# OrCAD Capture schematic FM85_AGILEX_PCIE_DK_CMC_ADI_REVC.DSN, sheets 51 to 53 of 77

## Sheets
51 System MAX10 3: size B
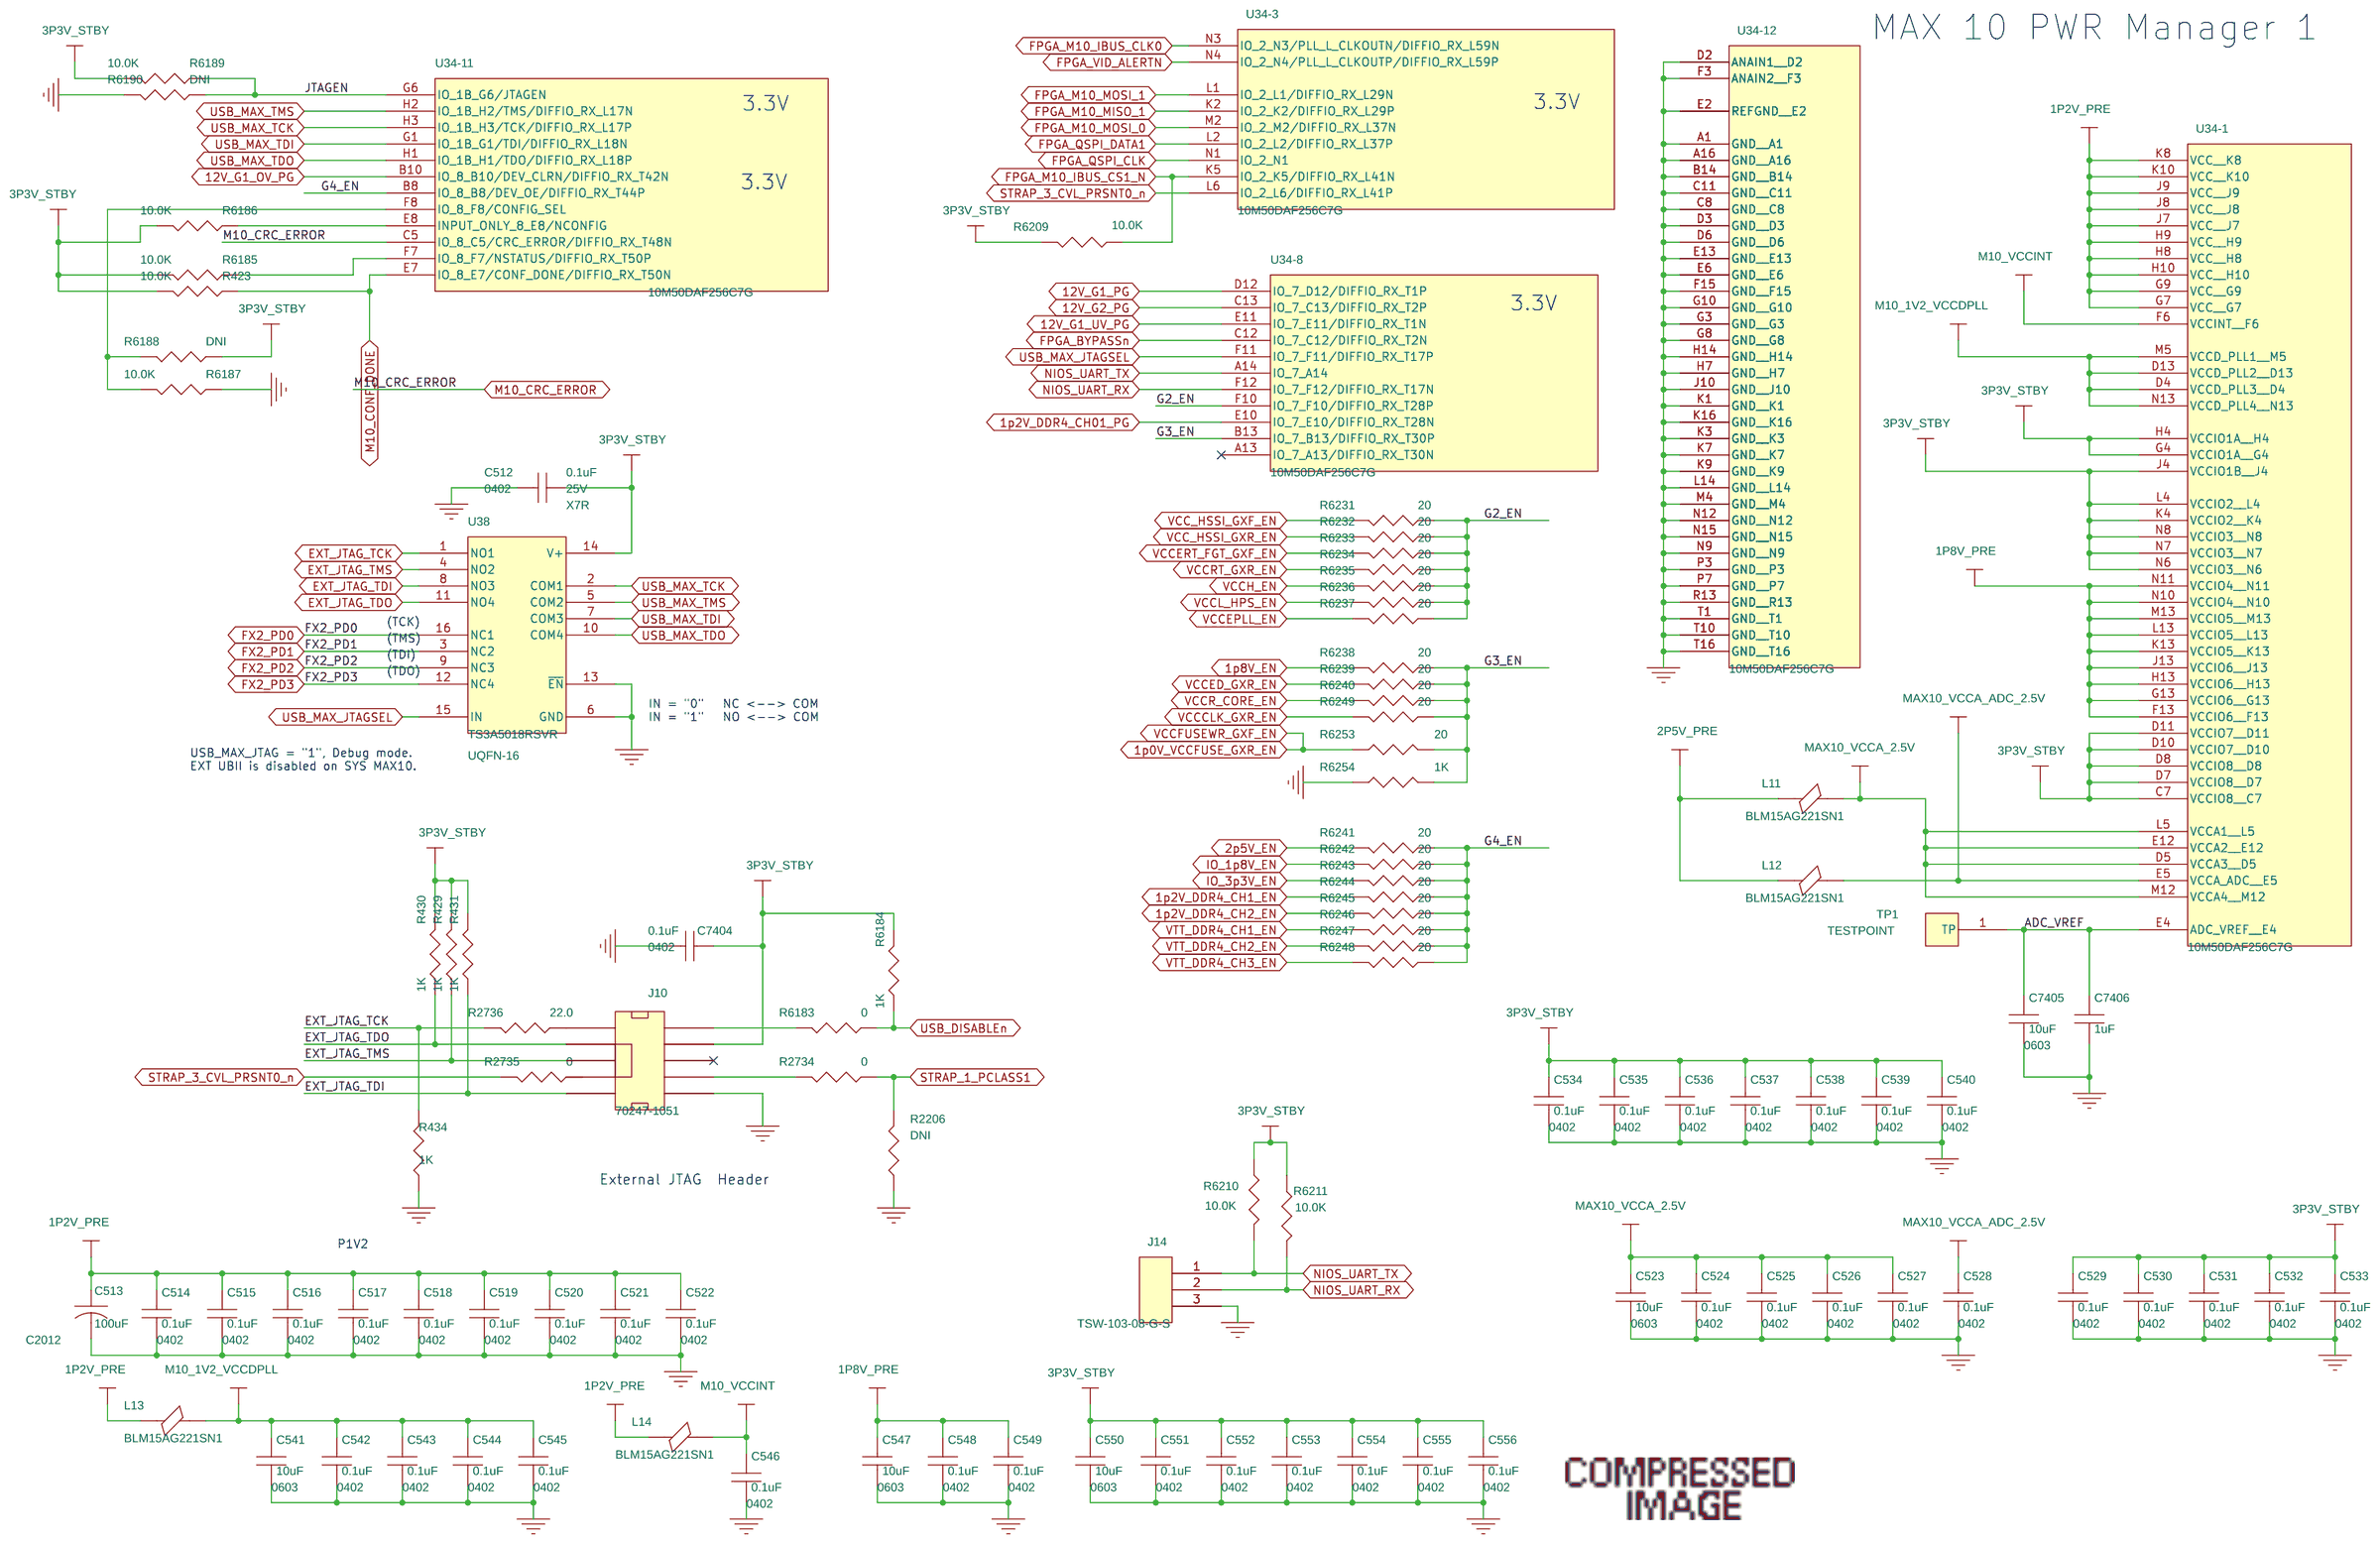
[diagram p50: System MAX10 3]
52 Level Shifter: size B
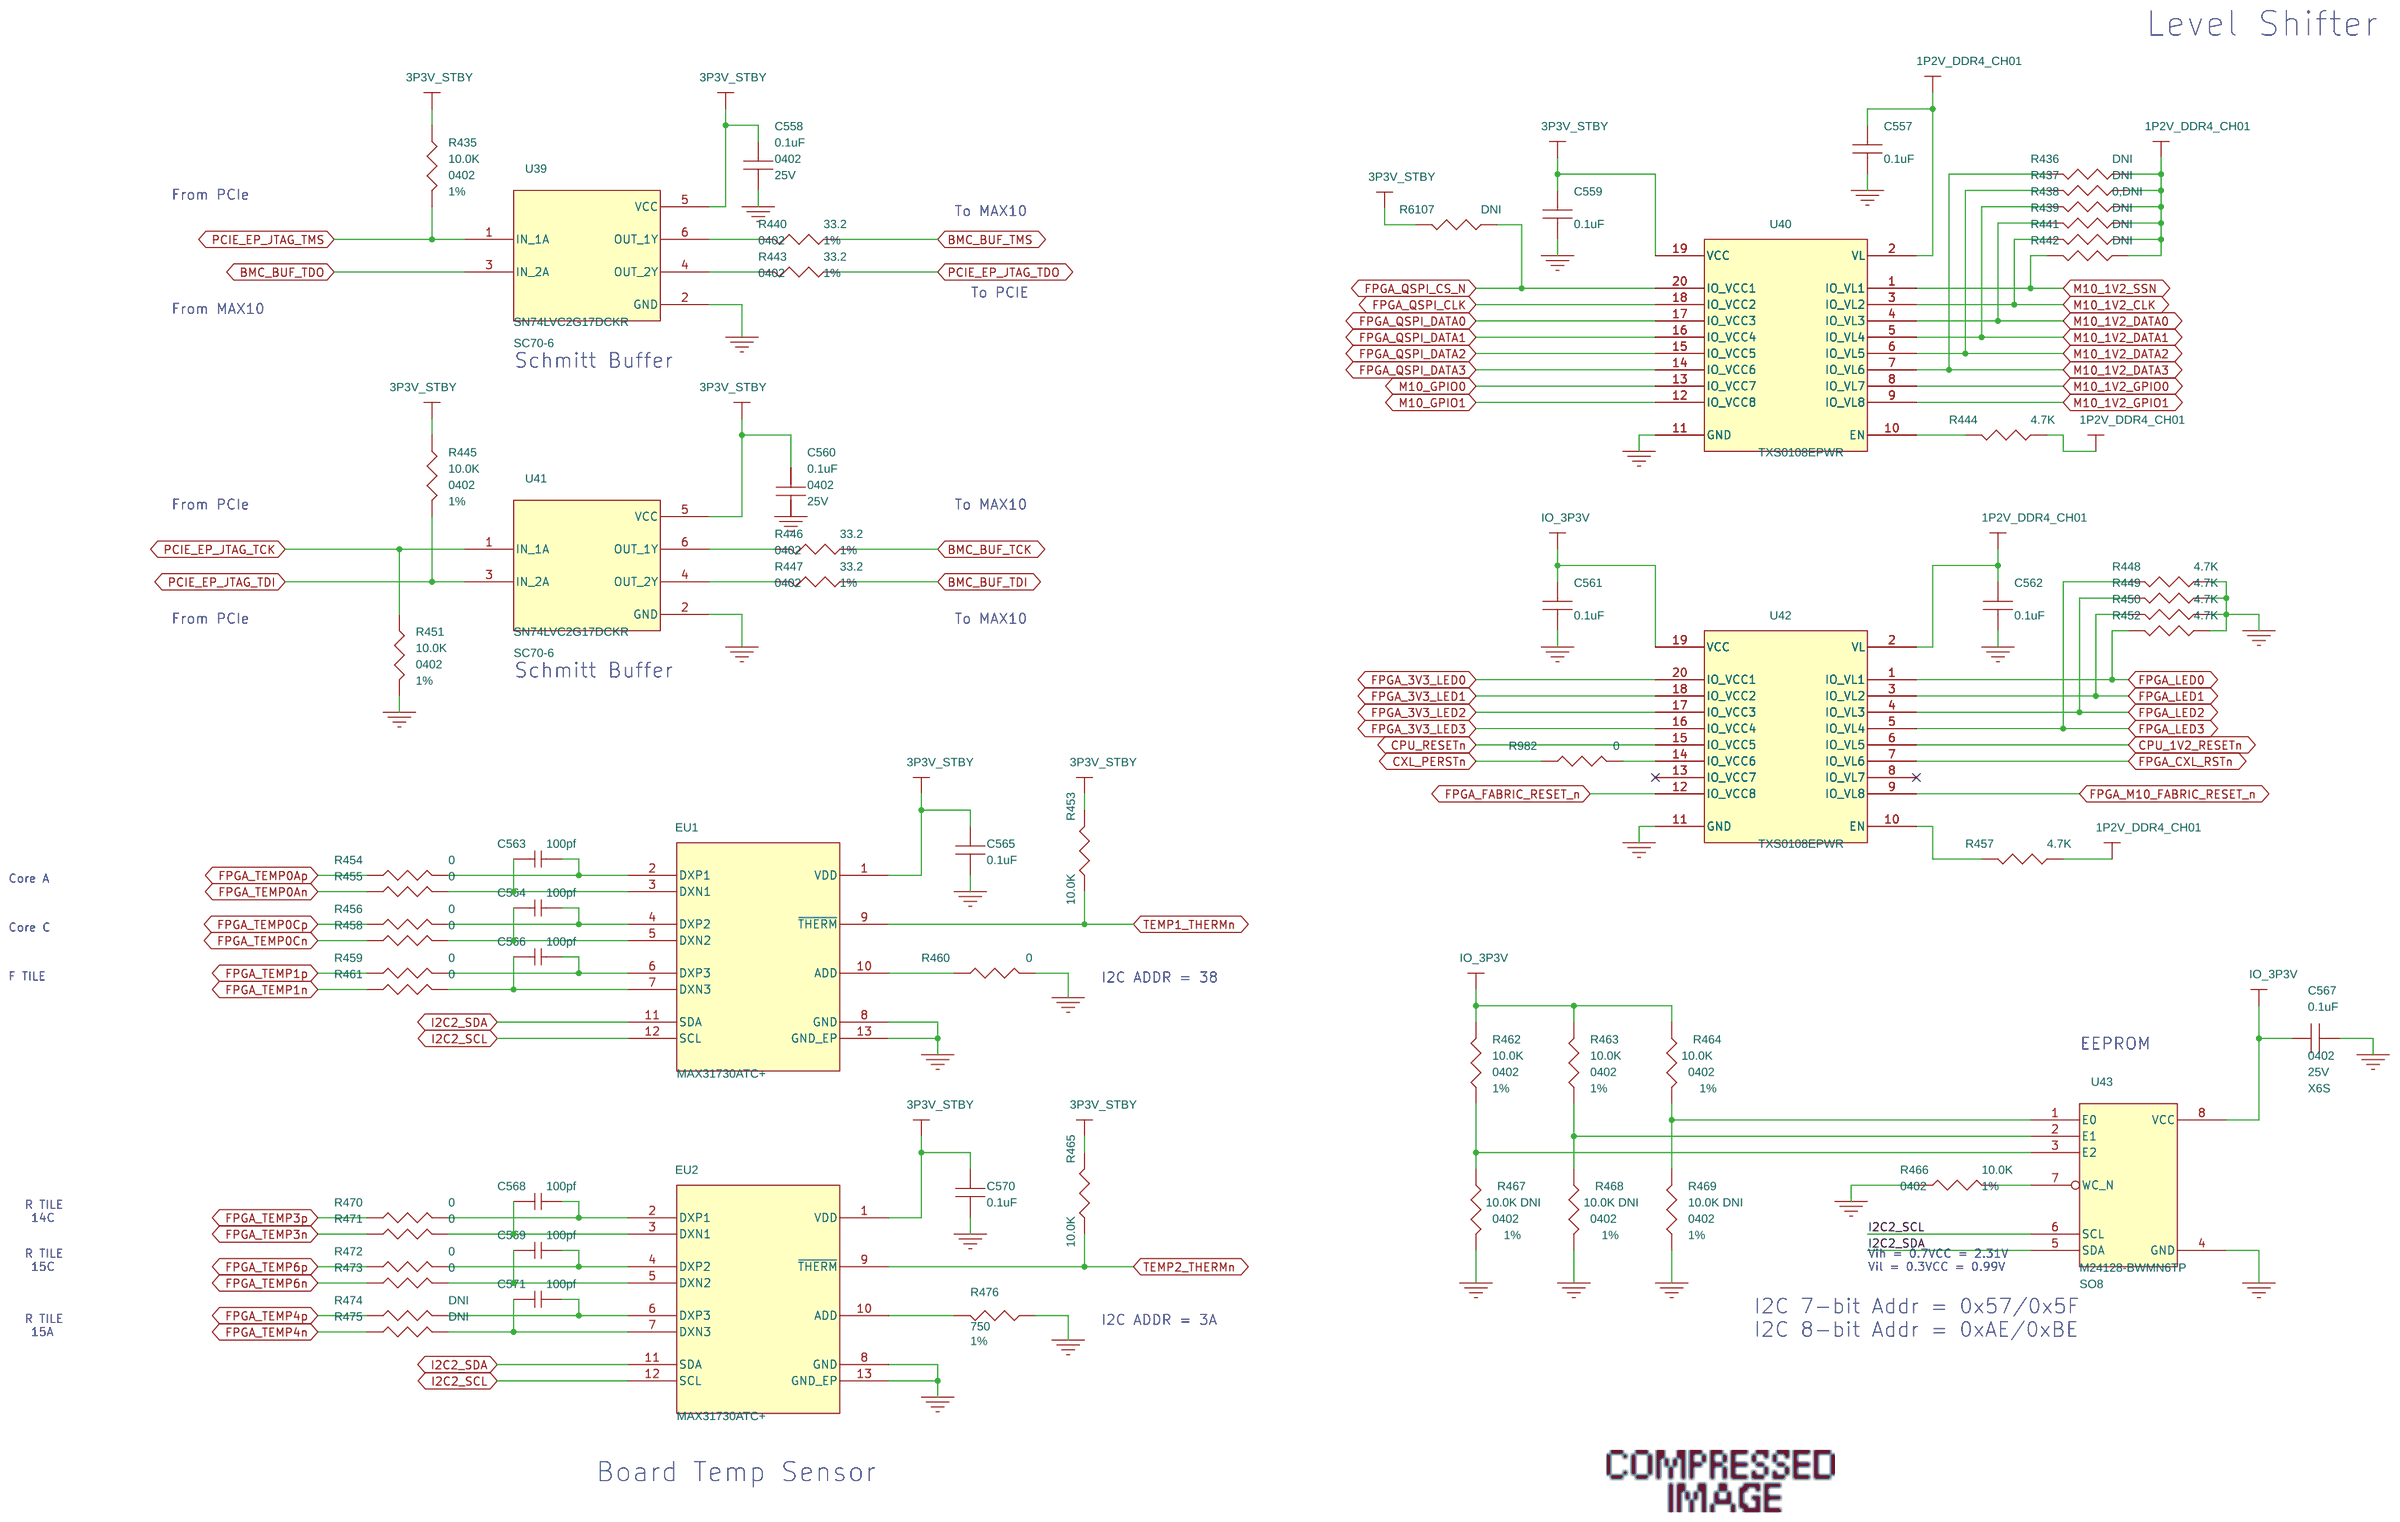
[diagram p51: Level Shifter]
53 Power Inputs: size Custom
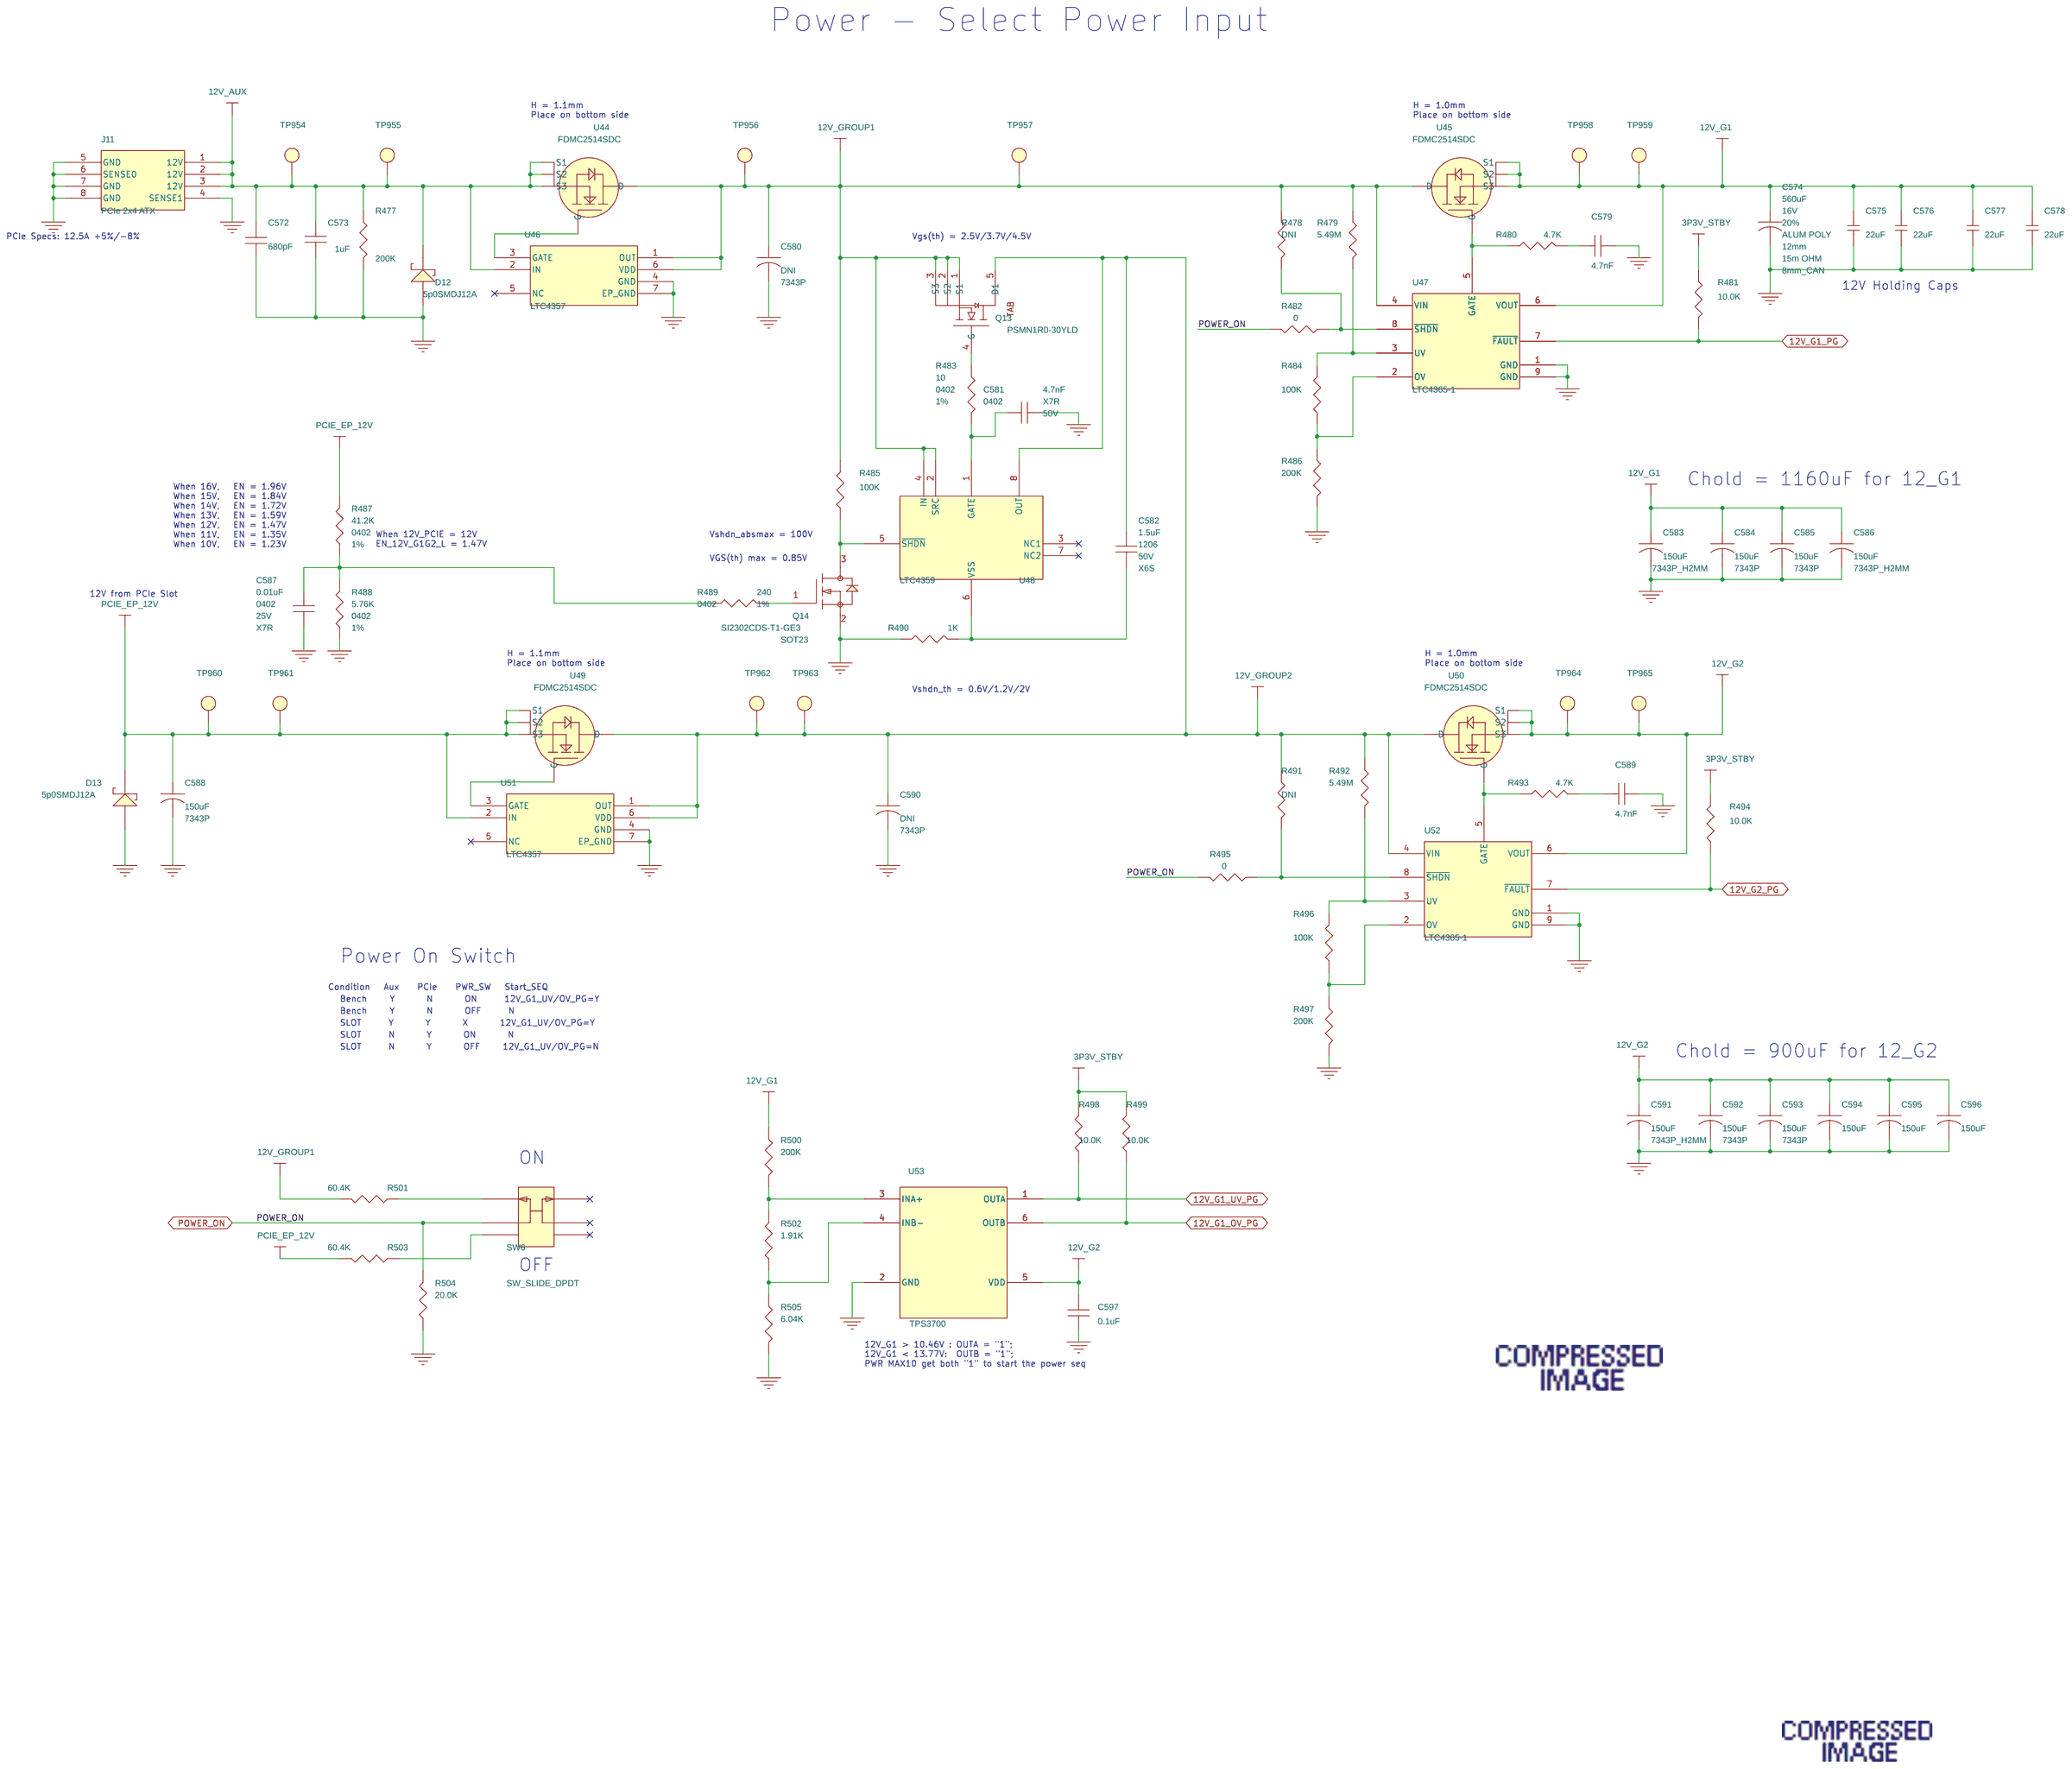
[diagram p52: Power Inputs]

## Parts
sheet Level Shifter
C557  0.1uF  [0402]
C558  0.1uF  [0402]
C559  0.1uF  [0402]
C560  0.1uF  [0402]
C561  0.1uF  [0402]
C562  0.1uF  [0402]
C563  100pf  [0402]
C564  100pf  [0402]
C565  0.1uF  [0402]
C566  100pf  [0402]
C567  0.1uF  [0402]
C568  100pf  [0402]
C569  100pf  [0402]
C570  0.1uF  [0402]
C571  100pf  [0402]
EU1  MAX31730ATC+  [lcc12_s30_50df25x17ma]
EU2  MAX31730ATC+  [lcc12_s30_50df25x17ma]
R435  10.0K  [0402]
R436  DNI  [0402]
R437  DNI  [0402]
R438  0,DNI  [0402]
R439  DNI  [0402]
R440  33.2  [0402]
R441  DNI  [0402]
R442  DNI  [0402]
R443  33.2  [0402]
R444  4.7K  [0402]
R445  10.0K  [0402]
R446  33.2  [0402]
R447  33.2  [0402]
R448  4.7K  [0402]
R449  4.7K  [0402]
R450  4.7K  [0402]
R451  10.0K  [0402]
R452  4.7K  [0402]
R453  10.0K  [0402]
R454  0  [0402]
R455  0  [0402]
R456  0  [0402]
R457  4.7K  [0402]
R458  0  [0402]
R459  0  [0402]
R460  0  [0402]
R461  0  [0402]
R462  10.0K  [0402]
R463  10.0K  [0402]
R464  10.0K  [0402]
R465  10.0K  [0402]
R466  10.0K  [0402]
R467  10.0K DNI  [0402]
R468  10.0K DNI  [0402]
R469  10.0K DNI  [0402]
R470  0  [0402]
R471  0  [0402]
R472  0  [0402]
R473  0  [0402]
R474  DNI  [0402]
R475  DNI  [0402]
R476  750  [0402]
R982  0  [0402]
R6107  DNI  [0402]
U39  SN74LVC2G17DCKR  [SC70-6]
U40  TXS0108EPWR  [20-TSSOP]
U41  SN74LVC2G17DCKR  [SC70-6]
U42  TXS0108EPWR  [20-TSSOP]
U43  M24128-BWMN6TP  [SO8]
sheet Power Inputs
C572  680pF  [0402]
C573  1uF  [0402]
C574  560uF  [8mm_CAN]
C575  22uF  [1206]
C576  22uF  [1206]
C577  22uF  [1206]
C578  22uF  [1206]
C579  4.7nF  [0402]
C580  DNI  [7343P]
C581  4.7nF  [0402]
C582  1.5uF  [1206]
C583  150uF  [7343P_H2MM]
C584  150uF  [7343P]
C585  150uF  [7343P]
C586  150uF  [7343P_H2MM]
C587  0.01uF  [0402]
C588  150uF  [7343P]
C589  4.7nF  [0402]
C590  DNI  [7343P]
C591  150uF  [7343P_H2MM]
C592  150uF  [7343P]
C593  150uF  [7343P]
C594  150uF  [7343P_H2MM]
C595  150uF  [7343P_H2MM]
C596  150uF  [7343P_H2MM]
C597  0.1uF  [0402]
D12  5p0SMDJ12A  [TVS_5p0SMDJ12A]
D13  5p0SMDJ12A  [TVS_5p0SMDJ12A]
J11  PCIe 2x4 ATX  [MLX_SD-5569_8POS_RA]
Q13  PSMN1R0-30YLD  [NFET_PSMN1R0-30YLD]
Q14  SI2302CDS-T1-GE3  [SOT23]
R477  200K  [0402]
R478  DNI  [0402]
R479  5.49M  [0402]
R480  4.7K  [0402]
R481  10.0K  [0402]
R482  0  [0402]
R483  10  [0402]
R484  100K  [0402]
R485  100K  [0402]
R486  200K  [0402]
R487  41.2K  [0402]
R488  5.76K  [0402]
R489  240  [0402]
R490  1K  [0402]
R491  DNI  [0402]
R492  5.49M  [0402]
R493  4.7K  [0402]
R494  10.0K  [0402]
R495  0  [0402]
R496  100K  [0402]
R497  200K  [0402]
R498  10.0K  [0402]
R499  10.0K  [0402]
R500  200K  [0402]
R501  60.4K  [0402]
R502  1.91K  [0402]
R503  60.4K  [0402]
R504  20.0K  [0402]
R505  6.04K  [0402]
SW6  SW_SLIDE_DPDT  [EG2207]
TP954  TESTPOINT  [30MIL_TP]
TP955  TESTPOINT  [30MIL_TP]
TP956  TESTPOINT  [30MIL_TP]
TP957  TESTPOINT  [30MIL_TP]
TP958  TESTPOINT  [30MIL_TP]
TP959  TESTPOINT  [30MIL_TP]
TP960  TESTPOINT  [30MIL_TP]
TP961  TESTPOINT  [30MIL_TP]
TP962  TESTPOINT  [30MIL_TP]
TP963  TESTPOINT  [30MIL_TP]
TP964  TESTPOINT  [30MIL_TP]
TP965  TESTPOINT  [30MIL_TP]
U44  FDMC2514SDC  [FDMC8878_VER2]
U45  FDMC2514SDC  [FDMC8878_VER2]
U46  LTC4357  [dfn6_epad]
U47  LTC4365-1  [DFN8-EPAD_3X2]
U48  LTC4359  [MSOP-8]
U49  FDMC2514SDC  [FDMC8878_VER2]
U50  FDMC2514SDC  [FDMC8878_VER2]
U51  LTC4357  [dfn6_epad]
U52  LTC4365-1  [DFN8-EPAD_3X2]
U53  TPS3700  [DDC]
sheet System MAX10 3
C512  0.1uF  [0402]
C513  100uF  [C2012]
C514  0.1uF  [0402]
C515  0.1uF  [0402]
C516  0.1uF  [0402]
C517  0.1uF  [0402]
C518  0.1uF  [0402]
C519  0.1uF  [0402]
C520  0.1uF  [0402]
C521  0.1uF  [0402]
C522  0.1uF  [0402]
C523  10uF  [0603]
C524  0.1uF  [0402]
C525  0.1uF  [0402]
C526  0.1uF  [0402]
C527  0.1uF  [0402]
C528  0.1uF  [0402]
C529  0.1uF  [0402]
C530  0.1uF  [0402]
C531  0.1uF  [0402]
C532  0.1uF  [0402]
C533  0.1uF  [0402]
C534  0.1uF  [0402]
C535  0.1uF  [0402]
C536  0.1uF  [0402]
C537  0.1uF  [0402]
C538  0.1uF  [0402]
C539  0.1uF  [0402]
C540  0.1uF  [0402]
C541  10uF  [0603]
C542  0.1uF  [0402]
C543  0.1uF  [0402]
C544  0.1uF  [0402]
C545  0.1uF  [0402]
C546  0.1uF  [0402]
C547  10uF  [0603]
C548  0.1uF  [0402]
C549  0.1uF  [0402]
C550  10uF  [0603]
C551  0.1uF  [0402]
C552  0.1uF  [0402]
C553  0.1uF  [0402]
C554  0.1uF  [0402]
C555  0.1uF  [0402]
C556  0.1uF  [0402]
C7404  0.1uF  [0402]
C7405  10uF  [0603]
C7406  1uF  [0402]
J10  70247-1051  [Molex_70247-1051]
J14  TSW-103-08-G-S  [1x3_HDR_TH]
L11  BLM15AG221SN1  [0402]
L12  BLM15AG221SN1  [0402]
L13  BLM15AG221SN1  [0402]
L14  BLM15AG221SN1  [0402]
R423  10.0K  [0402]
R429  1K  [0402]
R430  1K  [0402]
R431  1K  [0402]
R434  1K  [0402]
R2206  DNI  [0402]
R2734  0  [0402]
R2735  0  [0402]
R2736  22.0  [0402]
R6183  0  [0402]
R6184  1K  [0402]
R6185  10.0K  [0402]
R6186  10.0K  [0402]
R6187  10.0K  [0402]
R6188  DNI  [0402]
R6189  10.0K  [0402]
R6190  DNI  [0402]
R6209  10.0K  [0402]
R6210  10.0K  [0402]
R6211  10.0K  [0402]
R6231  20  [0402]
R6232  20  [0402]
R6233  20  [0402]
R6234  20  [0402]
R6235  20  [0402]
R6236  20  [0402]
R6237  20  [0402]
R6238  20  [0402]
R6239  20  [0402]
R6240  20  [0402]
R6241  20  [0402]
R6242  20  [0402]
R6243  20  [0402]
R6244  20  [0402]
R6245  20  [0402]
R6246  20  [0402]
R6247  20  [0402]
R6248  20  [0402]
R6249  20  [0402]
R6253  20  [0402]
R6254  1K  [0402]
TP1  TESTPOINT  [30mil_TP]
U34  10M50DAF256C7G  [256FBGA]  (sections -1,-10,-11,-12,-2,-3,-4,-5,-6,-7,-8,-9)
U38  TS3A5018RSVR  [UQFN-16]

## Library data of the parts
C557 C559 C561 C562 = CAP: CAPC,  X7R, 0402, 0.1uF, 25V, ±20%; Item Num: K13660-001; LIFECYCLE_PHASE: Active; Lead Free Status: Lead Free; MFR_LIFECYCLE: Active; Manufacturer: Murata; Manufacturer Part Num: GRM155R71E104KE14D; Num Pins: 2; PART_SUBCLASS: CAPACITORS; Part Class: CAPACITORS; RATED_VOLTAGE: 25V; RoHS Compliant: RoHS Compliant; Tolerance: +80%/-20%
C558 C560 = CAP: CAPC,  X7R, 0402, 0.1uF, 25V, ±20%; Item Num: K13660-001; LIFECYCLE_PHASE: Active; Lead Free Status: Lead Free; Manufacturer: Murata; Manufacturer Part Num: GRM155R71E104KE14D; Num Pins: 2; Part Class: CAPACITORS; RATED_VOLTAGE: 25V; RoHS Compliant: RoHS Compliant; Tolerance: +80%/-20%
C563 C564 C566 C568 C569 C571 = Cap,_NP,_0402: CAP, CERAMIC, 100pF, 0402, 5%, 50VDC, NPO; Item Num: K13768-001; Manufacturer: Murata; Manufacturer Part Num: GRM1555C1H101JA01D
C565 C570 C597 = CAP: CAPC,  X7R, 0402, 0.1uF, 25V, ±20%; AGILE_LINK: http://sj-agile9app/Agile/PLMServlet?action=OpenEmailObject&classid=10000&objid=213459527; Item Num: K13660-001; LIFECYCLE_PHASE: Active; Lead Free Status: Lead Free; MFR_LIFECYCLE: Active; Manufacturer: Murata; Manufacturer Part Num: GRM155R71E104KE14D; Num Pins: 2; PART_SUBCLASS: CAPACITORS; Part Class: CAPACITORS; RATED_VOLTAGE: 25V; RoHS Compliant: RoHS Compliant; TOLERANCE: +80%/-20%
C567 = CAP: CAPC,  X7R, 0402, 0.1uF, 25V, ±20%; Dielectric: X6S; Item Num: K13660-001; LIFECYCLE_PHASE: Active; Lead Free Status: Lead Free; Manufacturer: Murata; Manufacturer Part Num: GRM155R71E104KE14D; Num Pins: 2; Part Class: CAPACITORS; RATED_VOLTAGE: 25V; RoHS Compliant: RoHS Compliant; Tolerance: 10%
EU1 EU2 = MAX31730ATC: IC, MAX31730, 3-Ch Remote Temp Sensor; Item Num: K87190-001; Manufacturer: Maxim
R435 R445 R451 = RESISTOR: RES,10.0K OHMS,1.0%,1/16W, 0402; AGILE_LINK: http://sj-agile9app/Agile/PLMServlet?action=OpenEmailObject&classid=10000&objid=146548997; Agile IPN: P02-11364R; Item Num: K28115-001; LIFECYCLE_PHASE: Active; Lead Free Status: No; MFR_LIFECYCLE: Active; Manufacturer: Panasonic; Manufacturer Part Num: ERJ-2RKF1002X; Num Pins: 2; PART_SUBCLASS: RESISTORS; POWER: 1/16W; RESISTANCE: 10K; RoHS Compliant: Yes; TOLERANCE: 1%
R436 R437 R439 R441 R442 R444 R448-R450 R452 R457 R480 R493 R6107 = RESISTOR: RES 4.7K OHM 1/16W 5% 0402 SMD; Item Num: A93549-020; Lead Free Status: No; Manufacturer: Panasonic; Manufacturer Part Num: ERJ-2GEJ472X; Manufacturer's Part No.: ERJ-2GEJ472X; Num Pins: 2; Part Class: RESISTORS; Price: 0; RoHS Compliant: Yes
R438 = RESISTOR: RES D,0402,0.00 OHM,5.00%,1/16W; Item Num: A93549-001; Lead Free Status: No; Manufacturer: Panasonic; Manufacturer Part Num: ERJ-2GEJ472X; Manufacturer's Part No.: ERJ-2GEJ472X; Num Pins: 2; Part Class: RESISTORS; Price: 0; RoHS Compliant: Yes
R440 R443 R446 R447 = RESISTOR: RES,33.2 OHMS,1.0%,1/16W,0402; AGILE_LINK: http://sj-agile9app/Agile/PLMServlet?action=OpenEmailObject&classid=10000&objid=146932246; Agile IPN: P02-11379R; Item Num: E61624-001; LIFECYCLE_PHASE: Active; MFR_LIFECYCLE: Active; Manufacturer: Panasonic; Manufacturer Part Num: ERJ-2RKF33R2X; Num Pins: 2; PART_SUBCLASS: RESISTORS; POWER: 1/16W; RESISTANCE: 10; RoHS Compliant: RoHS Compliant; TOLERANCE: 1%
R423 R453 R465 R481 R494 R498 R499 R6185-R6187 R6189 R6209-R6211 = RESISTOR: RES,10.0K OHMS,1.0%,1/16W, 0402; AGILE_LINK: http://sj-agile9app/Agile/PLMServlet?action=OpenEmailObject&classid=10000&objid=146548997; Item Num: K28115-001; LIFECYCLE_PHASE: Active; Lead Free Status: No; MFR_LIFECYCLE: Active; Manufacturer: Panasonic; Manufacturer Part Num: ERJ-2RKF1002X; Num Pins: 2; PART_SUBCLASS: RESISTORS; POWER: 1/16W; RoHS Compliant: Yes; TOLERANCE: +/-1%
R454-R456 R458-R461 R470-R473 R982 = RESISTOR: RES ZERO OHM 1/16W 5% 0402 SMD; Altera Part No.: P02-14020R; Item Num: H30887-001; Lead Free Status: No; Manufacturer: Panasonic; Manufacturer Part Num: ERJ-2GE0R00X; Num Pins: 2; Part Class: RESISTORS; RoHS Compliant: Yes; Tolerance: 5%
R462-R464 R466-R469 = RESISTOR: RES,10.0K OHMS,1.0%,1/16W, 0402; AGILE_LINK: http://sj-agile9app/Agile/PLMServlet?action=OpenEmailObject&classid=10000&objid=146548997; Item Num: K28115-001; LIFECYCLE_PHASE: Active; Lead Free Status: No; MFR_LIFECYCLE: Active; Manufacturer: Panasonic; Manufacturer Part Num: ERJ-2RKF1002X; Num Pins: 2; PART_SUBCLASS: RESISTORS; POWER: 1/16W; RESISTANCE: 10K; RoHS Compliant: Yes; TOLERANCE: 1%
R474 R475 = RESISTOR: RES ZERO OHM 1/16W 5% 0402 SMD; Altera Part No.: P02-14020R; Item Num: H30887-001; Lead Free Status: No; Manufacturer: Panasonic; Manufacturer Part Num: ERJ-2GE0R00X; Num Pins: 2; Part Class: RESISTORS; Price: 0; RoHS Compliant: Yes; Tolerance: 5%
R476 = RESISTOR: RES SMD 750 OHM 1% 1/16W 0402; Item Num: G60609-020; Manufacturer: Yageo; Manufacturer Part Num: RC0402FR-07750RL; Num Pins: 2; Part Class: Resistors; TOLERANCE: 1%
U39 U41 = SN74LVC2G17DCKR: IC - Dual Schmitt-Trigger Buffer; Agile IPN: P01-18210R; Item Num: K21749-001; Manufacturer: Texas Instruments
U40 U42 = MAX3002EUP+T: IC TRNSLTR BIDIRECTIONAL 20TSSOP; Item Num: G13285-001; Manufacturer: Texa Instrument
U43 = M24128: IC EEPROM 128KBIT 400KHZ 8SO; Item Num: K21780-001; Manufacturer: STMicroelectronics
C572 = CAP: CAP - CER, 680pF, 10%, 50V, X7R, 0402; Item Num: A36096-015; LIFECYCLE_PHASE: Active; MFR_LIFECYCLE: Active; Manufacturer: Murata; Manufacturer Part Num: GRM155R71H681KA01D; Num Pins: 2; PART_SUBCLASS: CAPACITORS; RATED_VOLTAGE: 50V; RoHS Compliant: RoHS Compliant; TOLERANCE: +/-10%
C573 = CAP: CAP - CER, 1UF, 25V, 10%, X5R, 0402; Item Num: H29050-001; Lead Free Status: Yes; Manufacturer: TDK Electronics; Manufacturer Part Num: CGB2A1X5R1E105K033BC; Num Pins: 2; Part Class: CAPACITORS; RoHS Compliant: Yes
C574 = PCAP: 560µF ±20% 16V Aluminum Polymer Capacitor Radial, Can - SMD 14 mOhm 5000 Hrs @ 105°C; AGILE_LINK: http://sj-agile9app/Agile/PLMServlet?action=OpenEmailObject&classid=10000&objid=257237054; ESR: 15m OHM; Height: 12mm; Item Num: K22159-001; LIFECYCLE_PHASE: Active; Lead Free Status: Lead Free; MFR_LIFECYCLE: Active; Manufacturer: Panasonic; Manufacturer Part Num: 16SVPF560M; Num Pins: 2; PART_SUBCLASS: CAPACITORS; RATED_VOLTAGE: 16V; RoHS Compliant: RoHS Compliant; TOLERANCE: 20%; TYPE: ALUM POLY
C575-C578 = Cap,_NP,_1206: CAP - CER, 22UF, 25V, 10%, X5R, 1206; Item Num: K28232-001; Manufacturer: Murata; Manufacturer Part Num: GRM31CR61E226KE15L
C579 C589 = CAP: CAP CER 4700PF 50V 10% X7R 0402; AGILE_LINK: http://sj-agile9app/Agile/PLMServlet?action=OpenEmailObject&classid=10000&objid=256989767; CAPACITANCE: 15000pF; Item Num: K13700-001; LIFECYCLE_PHASE: Active; Lead Free Status: Lead Free; MFR_LIFECYCLE: Active; Manufacturer: Murata; Manufacturer Part Num: GRM155R71H472KA01J; Num Pins: 2; PART_SUBCLASS: CAPACITORS; RATED_VOLTAGE: 50V; RoHS Compliant: RoHS Compliant; TOLERANCE: 10%
C580 = PCAP: CAP - TANT POLYMER,150UF,16V,50MOHM ESR20%, 7343*1.8MM; CAPACITANCE: 150uF; LIFECYCLE_PHASE: Active; Lead Free Status: Lead Free; MFR_LIFECYCLE: Active; Manufacturer: Panasonic; Manufacturer Part Num: 16TQC150MYF; Num Pins: 2; PART_SUBCLASS: CAPACITORS; RATED_VOLTAGE: 16V; RoHS Compliant: RoHS Compliant; TOLERANCE: +/-20%
C581 = CAP: CAP CER 4700PF 50V 10% X7R 0402; AGILE_LINK: http://sj-agile9app/Agile/PLMServlet?action=OpenEmailObject&classid=10000&objid=256989767; CAPACITANCE: 4700pF; Item Num: K13700-001; LIFECYCLE_PHASE: Active; Lead Free Status: Lead Free; MFR_LIFECYCLE: Active; Manufacturer: Murata; Manufacturer Part Num: GRM155R71H472KA01J; Num Pins: 2; PART_SUBCLASS: CAPACITORS; RATED_VOLTAGE: 50V; RoHS Compliant: RoHS Compliant; TOLERANCE: 10%; Temperature Coefficient: X7R
C582 = CAP: CAP CER 1.5UF 50V X6S 1206; CAPACITANCE: 0.1uF; Dielectric: X6S; Item Num: K19472-001; LIFECYCLE_PHASE: Active; Lead Free Status: Lead Free; Manufacturer: Murata; Manufacturer Part Num: GRT31CC81H155KE01L; Num Pins: 2; Part Class: CAPACITORS; RATED_VOLTAGE: 50V; RoHS Compliant: RoHS Compliant; Tolerance: 10%
C583 C586 C591 C594-C596 = PCAP: CAPS,TA-P,D20,150.00uF,16.00V,+/- 20%,D20; Item Num: H97831-001; LIFECYCLE_PHASE: Active; Lead Free Status: Lead Free; MFR_LIFECYCLE: Active; Manufacturer: Panasonic; Manufacturer Part Num: 1CTQC15173F1; Num Pins: 2; PART_SUBCLASS: CAPACITORS; RATED_VOLTAGE: 16V; RoHS Compliant: RoHS Compliant; TOLERANCE: +/-20%
C584 C585 C588 C592 C593 = PCAP: CAP - TANT POLYMER,150UF,16V,50MOHM ESR20%, 7343*1.8MM; Item Num: G46681-001; LIFECYCLE_PHASE: Active; Lead Free Status: Lead Free; MFR_LIFECYCLE: Active; Manufacturer: Panasonic; Manufacturer Part Num: 16TQC150MYF; Num Pins: 2; PART_SUBCLASS: CAPACITORS; RATED_VOLTAGE: 16V; RoHS Compliant: RoHS Compliant; TOLERANCE: +/-20%
C587 = CAP: CAP CER 10000PF 25V X7R 0402; AGILE_LINK: http://sj-agile9app/Agile/PLMServlet?action=OpenEmailObject&classid=10000&objid=242850622; Item Num: A36096-008; LIFECYCLE_PHASE: Active; MFR_LIFECYCLE: Active; Manufacturer: Murata; Manufacturer Part Num: GRM155R71E103KA01D; Num Pins: 2; PACKAGING: Tape & Reel (TR); PART_SUBCLASS: CAPACITORS; RATED_VOLTAGE: 25V; RoHS Compliant: RoHS Compliant; TOLERANCE: 10%; Temperature Coefficient: X7R
C590 = PCAP: CAP - TANT POLYMER,150UF,16V,50MOHM ESR20%, 7343*1.8MM; CAPACITANCE: 150uF; Item Num: G46681-001; LIFECYCLE_PHASE: Active; Lead Free Status: Lead Free; MFR_LIFECYCLE: Active; Manufacturer: Panasonic; Manufacturer Part Num: 16TQC150MYF; Num Pins: 2; PART_SUBCLASS: CAPACITORS; RATED_VOLTAGE: 16V; RoHS Compliant: RoHS Compliant; TOLERANCE: +/-20%
D12 D13 = TVS_5p0SMDJ12A: TVS DIODE 12VWM 19.9VC SMD; Item Num: J31279-001; Manufacturer: Littelfuse Inc.; Manufacturer Part Num: 5.0SMDJ12A
J11 = 2X4_PCIE_ATX_1: CONN,PCIE ATX,8POS HDR,4.2MM,R/A; Item Num: K11298-001; Manufacturer: MOLEX CONNECTOR CORPORATION; Manufacturer Part Num: 45586-0005
Q13 = PSMN1R0-30YLD_0: MOSFET, N-Channel, 30V, 1mOhm, 300A; Item Num: K21466-001; Manufacturer: Nexperia USA Inc.
Q14 = PWRMOSFET_EN_GSD_1: MOSFET N-CH 20V 2.6A SOT23-3; Item Num: K69552-001; Manufacturer: Vishay Siliconix
R477 R486 R497 = RES: RES - 200K OHM, 1/16W, 1%, 0402 SMD; Item Num: A93548-186; Manufacturer: Panasonic; Manufacturer Part Num: ERJ-2RKF2003X; Package: SMD; Part Class: RESISTORS; Type: Resistor
R478 R484 R485 R491 R496 = RESISTOR: RES, 100K OHMS, 1.0%, 1/16W, 0402; Item Num: E86804-001; Lead Free Status: No; Manufacturer: Panasonic; Manufacturer Part Num: ERJ-2RKF1003X; Num Pins: 2; Part Class: Resistors; Price: 0; RoHS Compliant: Yes
R479 R492 = RESISTOR: RES - 5.49M OHM, 1/16W, 1%, 0402 SMD; Item Num: K16257-001; Lead Free Status: Yes; Manufacturer: Vishay; Manufacturer Part Num: CRCW04025M49FKED; Num Pins: 2; Part Class: Resistors
R482 R495 = RES_0_OHM_5%_1_16W_0402_SMD: Item Num: H30887-001
R483 = RESISTOR: RES, 10 OHM, 1%, 1/16W, 0402; AGILE_LINK: http://sj-agile9app/Agile/PLMServlet?action=OpenEmailObject&classid=10000&objid=146932246; Item Num: A80345-001; LIFECYCLE_PHASE: Active; MFR_LIFECYCLE: Active; Manufacturer: Panasonic; Manufacturer Part Num: ERJ-2RKF10R0X; Num Pins: 2; PART_SUBCLASS: RESISTORS; POWER: 1/16W; RoHS Compliant: RoHS Compliant; TOLERANCE: 1%
R487 = RESISTOR: RES SMD 41.2K OHM 1% 1/10W 0402; AGILE_LINK: http://sj-agile9app/Agile/PLMServlet?action=OpenEmailObject&classid=10000&objid=146548997; Item Num: K16280-001; LIFECYCLE_PHASE: Active; Lead Free Status: No; MFR_LIFECYCLE: Active; Manufacturer: Panasonic; Manufacturer Part Num: ERJ-2RKF4122X; Num Pins: 2; PART_SUBCLASS: RESISTORS; POWER: 1/10W; RoHS Compliant: Yes; TOLERANCE: 1%
R488 = RESISTOR: RES SMD 5.76K OHM 1% 1/10W 0402; AGILE_LINK: http://sj-agile9app/Agile/PLMServlet?action=OpenEmailObject&classid=10000&objid=146548997; Item Num: K15735-001; LIFECYCLE_PHASE: Active; Lead Free Status: No; MFR_LIFECYCLE: Active; Manufacturer: Panasonic; Manufacturer Part Num: ERJ-2RKF5761X; Num Pins: 2; PART_SUBCLASS: RESISTORS; POWER: 1/10W; RoHS Compliant: Yes; TOLERANCE: 1%
R489 = RESISTOR: RES - 240 OHM, 1/16W, 1%, 0402 SMD; Altera Part No.: P02-15995R; Item Num: K11195-001; Manufacturer: Panasonic; Manufacturer Part Num: ERJ-2RKF2400X; Num Pins: 2; Part Class: RESISTORS; Price: 0; RoHS Compliant: Yes; Tolerance: 1%
R429-R431 R434 R490 R6184 R6254 = RESISTOR: RES,1.00K OHMS,1.0%,1/16W,0402; Item Num: G60609-021; Lead Free Status: No; Manufacturer: Panasonic; Manufacturer Part Num: ERJ-2RKF1001X; Num Pins: 2; Part Class: Resistors
R500 = RESISTOR: RES - 200K OHM, 1/16W, 1%, 0402 SMD; Item Num: A93548-186; Manufacturer: Panasonic; Manufacturer Part Num: ERJ-2RKF2003X; Tolerance: +/-1%
R501 R503 = RESISTOR: RES,60.4K,1/16W,1%,0402,SMD; Item Num: K15653-001; Manufacturer: Rohm; Manufacturer Part Num: MCR01MZPF6042
R502 = RESISTOR: RES - 1.91K OHM, 1%, 1/10W 0402 SMD; Item Num: D89469-001; Manufacturer: Panasonic; Manufacturer Part Num: ERJ-2RKF1911X; Tolerance: +/-1%
R504 = RESISTOR: RES 20.0K OHM 1/16W 1% 0402 SMD; Item Num: A78608-001; Lead Free Status: Yes; Manufacturer: Panasonic; Manufacturer Part Num: ERJ-2RKF2002X; Num Pins: 2; Part Class: RESISTORS; RoHS Compliant: Yes
R505 = RESISTOR: RES 6.04K OHM 1/16W 1% 0402 SMD; Item Num: A93548-197; Manufacturer: Vishay; Manufacturer Part Num: CRCW04026K04FKED; Tolerance: +/-1%
SW6 = SW_SLIDE_DPDT: SWITCH - SLIDE DPDT, 30V, 0.2AMP, Vertical; Item Num: J42686-001; Manufacturer: E-SWITCH
TP954-TP965 = TP,_0.016_,_Thru_Hole
U44 U45 U49 U50 = FDMC8878_VER2: MOSFET N-CHANNEL DUAL COOL PWR TRENCH 40A 25V 3.5mOHM; Item Num: K14521-001; Manufacturer: Fairchild Semiconductor
U46 U51 = LTC4357: IC - POSITIVE HIGH VOLTAGE IDEAL DIODE CONTROLLER, VIN 9V-80V, 6-LEAD DFN; AGILE_LINK: http://sj-agile9app/Agile/PLMServlet?action=OpenEmailObject&classid=10000&objid=259478351; Item Num: K64810-001; LIFECYCLE_PHASE: Preliminary; Lead Free Status: Lead Free; MFR_LIFECYCLE: Active; Manufacturer: Linear Technology; Manufacturer Part Num: LTC4357IDCB#xxxPBF; Num Pins: 7; PART_SUBCLASS: ICS; RoHS Compliant: RoHS Compliant
U47 U52 = LTC4365_DFN: IC - LT4365-1, DFN8, UV, OV, REVERSE SUPPLY PROTECTION, VIN=2.5V-34V, (3 X 2 X 0.75)MM, TEMP=-40C-125C; Item Num: K64807-001; LIFECYCLE_PHASE: Active; Lead Free Status: Lead Free; MFR_LIFECYCLE: Active; Manufacturer: Linear Technology; Manufacturer Part Num: LTC4365HDDB-1#TRMPBF; Num Pins: 9; PART_SUBCLASS: ICS; RoHS Compliant: RoHS Compliant
U48 = LTC4359: IC - Ideal Diode Controller with Reverse Input Protection; Item Num: K22140-001; Manufacturer: Linear Technology; Manufacturer Part Num: LTC4359IMS8#PBF
U53 = TPS3700: IC,LIN,COMPARATOR,SOT,TPS3700,DUAL; Item Num: J43211-001
C512 = CAP: CAP - CERAMIC,  0.1UF 0402 25VDC X7R; Dielectric: X7R; Item Num: K13560-001; LIFECYCLE_PHASE: Active; Lead Free Status: Lead Free; Manufacturer: Murata; Manufacturer Part Num: GRM155R71E104KE14D; Num Pins: 2; Part Class: CAPACITORS; RATED_VOLTAGE: 25V; RoHS Compliant: RoHS Compliant; Tolerance: 10%
C513 = PCAP: CAP TANT 100UF 20% 6.3V 0805; Item Num: K50217-001; LIFECYCLE_PHASE: Active; Lead Free Status: Lead Free; MFR_LIFECYCLE: Active; Manufacturer: Vishay Sprague; Manufacturer Part Num: 298D107X06R3P2T; Num Pins: 2; PART_SUBCLASS: CAPACITORS; RATED_VOLTAGE: 6.3V; RoHS Compliant: RoHS Compliant; TOLERANCE: +/-20%
C514-C516 C518-C520 C522 C524 C525 C527-C540 C542-C546 C548 C549 C551-C556 C7404 = CAP: CAPC,  X7R, 0402, 0.1uF, 25V, ±20%; Dielectric: X7R; Item Num: K13660-001; LIFECYCLE_PHASE: Active; Lead Free Status: Lead Free; Manufacturer: Murata; Manufacturer Part Num: GRM155R71E104KE14D; Num Pins: 2; Part Class: CAPACITORS; Price: 0.07; RATED_VOLTAGE: 25V; RoHS Compliant: RoHS Compliant; Tolerance: ±10%
C517 C521 C526 = CAP: CAPC,  X7R, 0402, 0.1uF, 25V, ±20%; Dielectric: X7R; Item Num: K13660-001; LIFECYCLE_PHASE: Active; Lead Free Status: Lead Free; Manufacturer: Murata; Manufacturer Part Num: GGRM155R71E104KE14D; Num Pins: 2; Part Class: CAPACITORS; Price: 0.07; RATED_VOLTAGE: 25V; RoHS Compliant: RoHS Compliant; Tolerance: ±10%
C523 C541 C547 C550 C7405 = CAP: CAP CER 10UF 6.3V X6S 0603; Agile IPN: P03-17964R; Item Num: K19402-001; Lead Free Status: Lead Free; Manufacturer: TDK; Manufacturer Part Num: C1608X6S0J106M080AC; Num Pins: 2; PART_SUBCLASS: CAPACITORS; Part Class: CAPACITORS; RATED_VOLTAGE: 6.3V; RoHS Compliant: RoHS Compliant; Temperature Coefficient: X6S
C7406 = CAP: CAP - CER, 1uF, 10V, +/-10%, X5R, 0402; Item Num: G61001-001; Lead Free Status: Yes; Manufacturer: Murata; Manufacturer Part Num: GRM155R61A105KE15D; Num Pins: 2; Part Class: CAPACITORS; RoHS Compliant: Yes
J10 = 70247-1051: CONN,HDR2X5 100 MIL,SHROUDED RIGHT-ANGLE; Device: J23; Item Num: K10905-001; Lead Free Status: No; Manufacturer: MOLEX CONNECTOR CORPORATION; Num Pins: 10; Part Class: Connectors; Price: 1; RoHS Compliant: Yes
J14 = 1x3_HDR_TH: 1X3 .100"CENTER HDR,.145" MIN SOLDER TAIL; Item Num: K12462-001; Manufacturer: Samtec
L11-L14 = BEAD_FERRITE_SM: IND - SMD EMI FILTERS/CHIP FERRITE BEAD, 220-OHM @ 100MHZ, 0.35-OHM DCR, 0402; Agile IPN: P04-16225R; Item Num: K14401-001; LIFECYCLE_PHASE: Active; MFR_LIFECYCLE: Active; Manufacturer: Murata; Manufacturer Part Num: BLM15AG221SN1x; Num Pins: 2; PART_SUBCLASS: INDUCTORS
R2206 = RES_VERT_HORIZ: RES ZERO OHM 1/16W 5% 0402 SMD; ALT_SYMBOLS: 0402CIR_M; Function: Resistor; Item Num: H30887-001; Lifecycle: Production; Manufacturer: Panasonic; Manufacturer Part Num: ERJ-2GE0R00X; Part Type: Resistor; Part_Number: ER#04024K7FT; Tolerance: 1%; Wattage: 1/16W
R2734 R2735 R6183 = RESISTOR: RES ZERO OHM 1/16W 5% 0402 SMD; Agile IPN: P02-14020R; Altera Part No.: P02-14020R; Item Num: H30887-001; Lead Free Status: No; Manufacturer: Panasonic; Manufacturer Part Num: ERJ-2GE0R00X; Num Pins: 2; Part Class: RESISTORS; RoHS Compliant: Yes; Tolerance: 5%
R2736 = RESISTOR: RES - 22.0 OHM, 1/16W, 1%, 0402 SMD; Agile IPN: P02-16269R; Item Num: K15746-001; Lead Free Status: Yes; Manufacturer: Panasonic; Manufacturer Part Num: ERJ-2RKF22R0X; Num Pins: 2; Part Class: Resistors; Price: 0
R6188 R6190 = RESISTOR: RES ZERO OHM 1/16W 5% 0402 SMD; Agile IPN: P02-14020R; Altera Part No.: P02-14020R; Item Num: H30887-001; Lead Free Status: No; Manufacturer: Panasonic; Manufacturer Part Num: ERJ-2GE0R00X; Num Pins: 2; Part Class: RESISTORS; Price: 0; RoHS Compliant: Yes; Tolerance: 5%
R6231-R6249 = RESISTOR: RES SMDRES D,0402,20.00 OHM,1.00%,1/16W; Item Num: A93548-053; Lead Free Status: No; Manufacturer: Vishay; Manufacturer Part Num: CRCW040220R0FKED; Num Pins: 2; Part Class: Resistors; TOLERANCE: 1%
R6253 = RESISTOR: RES D,0402,20.00 OHM,1.00%,1/16W,YES; Item Num: A93548-053; Lead Free Status: No; Manufacturer: YAGEO CORP.; Manufacturer Part Num: RC0402FR-0720RL; Num Pins: 2; Part Class: Resistors
TP1 = TESTPOINT
U34 = 10M50DA_F256: IC FPGA 178 I/O 256FBGA; Agile IPN: P01-18272R; Item Num: 973682; Manufacturer: Intel
U38 = TS3A5018RSVR_0: IC,LIN,ANALOGSWITCH,UQFN,TS3A5018,; Item Num: H28953-001; Manufacturer: Texas Instrument

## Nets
12V_AUX: C572.2 C573.1 D12.1(C) J11.1(12V) J11.2(12V) J11.3(12V) R477.1 TP954.1 TP955.1 U44.1(S1) U44.2(S2) U44.3(S3) U46.2(IN)
12V_G1: C574.1 C575.2 C576.2 C577.2 C578.2 C583.1 C584.1 C585.1 C586.1 R500.1 TP958.1 TP959.1 U45.1(S1) U45.2(S2) U45.3(S3) U47.6(VOUT) ; also on sheet 19 20 50 54 55 56
12V_G1_OV_PG: R499.1 U34.B10(IO_8_B10/DEV_CLRN/DIFFIO_RX_T42N) U53.6(OUTB)
12V_G1_PG: R481.2 U34.D12(IO_7_D12/DIFFIO_RX_T1P) U47.7(~{FAULT})
12V_G1_UV_PG: R498.1 U34.E11(IO_7_E11/DIFFIO_RX_T1N) U53.1(OUTA)
12V_G2: C591.1 C592.1 C593.1 C594.1 C595.1 C596.1 C597.2 TP964.1 TP965.1 U50.1(S1) U50.2(S2) U50.3(S3) U52.6(VOUT) U53.5(VDD) ; also on sheet 57 58 59 60 61 62 63 64 65 66 67 69 70 71 73
12V_G2_PG: R494.1 U34.C13(IO_7_C13/DIFFIO_RX_T2P) U52.7(~{FAULT})
12V_GROUP1: C580.1 Q13.1(S1) Q13.2(S2) Q13.3(S3) R478.1 R479.1 R485.1 R501.2 TP956.1 TP957.1 U44.5(D) U45.5(D) U46.1(OUT) U46.6(VDD) U47.4(VIN) U48.2(SRC) U48.4(IN)
12V_GROUP2: C582.1 C590.1 Q13.5(D1) R491.1 R492.1 TP962.1 TP963.1 U48.8(OUT) U49.5(D) U50.5(D) U51.1(OUT) U51.6(VDD) U52.4(VIN)
GND: C512.2 C513.2 C514.2 C515.2 C516.2 C517.2 C518.2 C519.2 C520.2 C521.2 C522.2 C523.2 C524.2 C525.2 C526.2 C527.2 C528.2 C529.2 C530.2 C531.2 C532.2 C533.2 C534.2 C535.2 C536.2 C537.2 C538.2 C539.2 C540.2 C541.2 C542.2 C543.2 C544.2 C545.2 C546.2 C547.2 C548.2 C549.2 C550.2 C551.2 C552.2 C553.2 C554.2 C555.2 C556.2 C557.2 C558.2 C559.2 C560.2 C561.2 C562.2 C565.2 C567.2 C570.2 C572.1 C573.2 C574.2 C575.1 C576.1 C577.1 C578.1 C579.1 C580.2 C581.2 C583.2 C584.2 C585.2 C586.2 C587.2 C588.2 C589.1 C590.2 C591.2 C592.2 C593.2 C594.2 C595.2 C596.2 C597.1 C7404.2 C7405.2 C7406.2 D12.2 D13.2 EU1.8(GND) EU1.13(GND_EP) EU2.8(GND) EU2.13(GND_EP) J10.10 J11.4(SENSE1) J11.5(GND) J11.6(SENSE0) J11.7(GND) J11.8(GND) J14.3 Q14.2(SOURCE) R434.2 R448.1 R449.1 R450.1 R451.2 R452.1 R460.2 R466.2 R467.1 R468.1 R469.1 R476.2 R477.2 R486.2 R488.2 R490.2 R497.2 R504.1 R505.2 R2206.1 R6187.1 R6190.1 R6254.2 U34.A1(GND_) U34.A16(GND_) U34.B14(GND_) U34.C8(GND_) U34.C11(GND_) U34.D2(ANAIN1_) U34.D3(GND_) U34.D6(GND_) U34.E2(REFGND_) U34.E6(GND_) U34.E13(GND_) U34.F3(ANAIN2_) U34.F15(GND_) U34.G3(GND_) U34.G8(GND_) U34.G10(GND_) U34.H7(GND_) U34.H14(GND_) U34.J10(GND_) U34.K1(GND_) U34.K3(GND_) U34.K7(GND_) U34.K9(GND_) U34.K16(GND_) U34.L14(GND_) U34.M4(GND_) U34.N9(GND_) U34.N12(GND_) U34.N15(GND_) U34.P3(GND_) U34.P7(GND_) U34.R13(GND_) U34.T1(GND_) U34.T10(GND_) U34.T16(GND_) U38.6(GND) U38.13(~{EN}) U39.2(GND) U40.11(GND) U41.2(GND) U42.11(GND) U43.4(GND) U46.4(GND) U46.7(EP_GND) U47.1(GND) U47.9(GND) U51.4(GND) U51.7(EP_GND) U52.1(GND) U52.9(GND) U53.2(GND) ; also on sheet 9 10 11 13 14 15 16 17 18 19 20 21 22 23 25 26 27 28 29 30 31 32 33 34 35 36 38 39 40 41 42 43 44 45 46 47 48 49 50 54 55 56 57 58 59 60 61 62 63 64 65 66 67 68 69 70 71 72 73 74 75 76 77
VCC_HSSI_GXF_EN: R6231.1 ; also on sheet 65
VCC_HSSI_GXR_EN: R6232.1 ; also on sheet 63
VCCCLK_GXR_EN: R6249.1 ; also on sheet 74
VCCED_GXR_EN: R6239.1 ; also on sheet 60
VCCEPLL_EN: R6237.1 ; also on sheet 69
VCCERT_FGT_GXF_EN: R6233.1 ; also on sheet 61
VCCH_EN: R6235.1 ; also on sheet 64
VCCL_HPS_EN: R6236.1 ; also on sheet 60
VCCR_CORE_EN: R6240.1 ; also on sheet 59
VCCRT_GXR_EN: R6234.1 ; also on sheet 62
1p0V_VCCFUSE_GXR_EN: R6253.2 ; also on sheet 74
1p2V_DDR4_CH01: C557.1 C562.1 R436.1 R437.1 R438.1 R439.1 R441.1 R442.1 R444.1 R457.1 U40.2(VL) U42.2(VL) ; also on sheet 9 10 11 14 15 16 32 39 46 47 70 72 76 77
1p2V_DDR4_CH1_EN: R6244.1 ; also on sheet 70
1p2V_DDR4_CH01_PG: U34.E10(IO_7_E10/DIFFIO_RX_T28N) ; also on sheet 70
1p2V_DDR4_CH2_EN: R6245.1 ; also on sheet 71
1p2V_PRE: C513.1 C514.1 C515.1 C516.1 C517.1 C518.1 C519.1 C520.1 C521.1 C522.1 L13.1 L14.1 U34.G7(VCC_) U34.G9(VCC_) U34.H8(VCC_) U34.H9(VCC_) U34.H10(VCC_) U34.J7(VCC_) U34.J8(VCC_) U34.J9(VCC_) U34.K8(VCC_) U34.K10(VCC_) ; also on sheet 68
1p8V_EN: R6238.1 ; also on sheet 66
1p8V_PRE: C547.1 C548.1 C549.1 U34.F13(VCCIO6_) U34.G13(VCCIO6_) U34.H13(VCCIO6_) U34.J13(VCCIO6_) U34.K13(VCCIO5_) U34.L13(VCCIO5_) U34.M13(VCCIO5_) U34.N10(VCCIO4_) U34.N11(VCCIO4_) ; also on sheet 35 49 50 68
2p5V_EN: R6241.1 ; also on sheet 73
2p5V_PRE: L11.1 L12.1 ; also on sheet 57
3p3V_STBY: C512.1 C529.1 C530.1 C531.1 C532.1 C533.1 C534.1 C535.1 C536.1 C537.1 C538.1 C539.1 C540.1 C550.1 C551.1 C552.1 C553.1 C554.1 C555.1 C556.1 C558.1 C559.1 C560.1 C565.1 C570.1 C7404.1 EU1.1(VDD) EU2.1(VDD) J10.4 R423.2 R429.1 R430.1 R431.1 R435.1 R445.1 R453.2 R465.2 R481.1 R494.2 R498.2 R499.2 R6107.2 R6184.1 R6185.2 R6186.2 R6188.2 R6189.2 R6209.2 R6210.1 R6211.1 U34.C7(VCCIO8_) U34.D7(VCCIO8_) U34.D8(VCCIO8_) U34.D10(VCCIO7_) U34.D11(VCCIO7_) U34.G4(VCCIO1A_) U34.H4(VCCIO1A_) U34.J4(VCCIO1B_) U34.K4(VCCIO2_) U34.L4(VCCIO2_) U34.N6(VCCIO3_) U34.N7(VCCIO3_) U34.N8(VCCIO3_) U38.14(V+) U39.5(VCC) U40.19(VCC) U41.5(VCC) ; also on sheet 30 44 48 49 50 57 77
ADC_VREF: C7405.1 C7406.1 TP1.1(TP) U34.E4(ADC_VREF_)
BMC_BUF_TCK: R446.1 ; also on sheet 50
BMC_BUF_TDI: R447.1 ; also on sheet 50
BMC_BUF_TDO: U39.3(IN_2A) ; also on sheet 50
BMC_BUF_TMS: R440.1 ; also on sheet 50
CPU_1V2_RESETn: U42.6(IO_VL5) ; also on sheet 12
CPU_RESETn: U42.15(IO_VCC5) ; also on sheet 48 49
CXL_PERSTn: R982.1 ; also on sheet 32 33 48
EXT_JTAG_TCK: R434.1 R2736.2 U38.1(NO1) ; also on sheet 50
EXT_JTAG_TDI: J10.9 R431.2 U38.8(NO3) ; also on sheet 50
EXT_JTAG_TDO: J10.3 R430.2 U38.11(NO4) ; also on sheet 50
EXT_JTAG_TMS: J10.5 R429.2 U38.4(NO2) ; also on sheet 50
FPGA_3V3_LED0: U42.20(IO_VCC1) ; also on sheet 48
FPGA_3V3_LED1: U42.18(IO_VCC2) ; also on sheet 48
FPGA_3V3_LED2: U42.17(IO_VCC3) ; also on sheet 48
FPGA_3V3_LED3: U42.16(IO_VCC4) ; also on sheet 48
FPGA_BYPASSn: U34.C12(IO_7_C12/DIFFIO_RX_T2N) ; also on sheet 50
FPGA_CXL_RSTn: U42.7(IO_VL6) ; also on sheet 22
FPGA_FABRIC_RESET_n: U42.12(IO_VCC8) ; also on sheet 48
FPGA_LED0: R452.2 U42.1(IO_VL1) ; also on sheet 22
FPGA_LED1: R450.2 U42.3(IO_VL2) ; also on sheet 22
FPGA_LED2: R449.2 U42.4(IO_VL3) ; also on sheet 22
FPGA_LED3: R448.2 U42.5(IO_VL4) ; also on sheet 22
FPGA_M10_FABRIC_RESET_n: U42.9(IO_VL8) ; also on sheet 22
FPGA_M10_IBUS_CLK0: U34.N3(IO_2_N3/PLL_L_CLKOUTN/DIFFIO_RX_L59N) ; also on sheet 77
FPGA_M10_IBUS_CS1_N: R6209.1 U34.K5(IO_2_K5/DIFFIO_RX_L41N) ; also on sheet 77
FPGA_M10_MISO_1: U34.K2(IO_2_K2/DIFFIO_RX_L29P) ; also on sheet 77
FPGA_M10_MOSI_0: U34.M2(IO_2_M2/DIFFIO_RX_L37N) ; also on sheet 77
FPGA_M10_MOSI_1: U34.L1(IO_2_L1/DIFFIO_RX_L29N) ; also on sheet 77
FPGA_QSPI_CLK: U34.N1(IO_2) U40.18(IO_VCC2)
FPGA_QSPI_CS_N: R6107.1 U40.20(IO_VCC1) ; also on sheet 49
FPGA_QSPI_DATA0: U40.17(IO_VCC3) ; also on sheet 49
FPGA_QSPI_DATA1: U34.L2(IO_2_L2/DIFFIO_RX_L37P) U40.16(IO_VCC4)
FPGA_QSPI_DATA2: U40.15(IO_VCC5) ; also on sheet 49
FPGA_QSPI_DATA3: U40.14(IO_VCC6) ; also on sheet 49
FPGA_TEMP0An: R455.2 ; also on sheet 35
FPGA_TEMP0Ap: R454.2 ; also on sheet 35
FPGA_TEMP0Cn: R458.2 ; also on sheet 29
FPGA_TEMP0Cp: R456.2 ; also on sheet 29
FPGA_TEMP1n: R461.2 ; also on sheet 28
FPGA_TEMP1p: R459.2 ; also on sheet 28
FPGA_TEMP3n: R471.2 ; also on sheet 31
FPGA_TEMP3p: R470.2 ; also on sheet 31
FPGA_TEMP4n: R475.2 ; also on sheet 34
FPGA_TEMP4p: R474.2 ; also on sheet 34
FPGA_TEMP6n: R473.2 ; also on sheet 33
FPGA_TEMP6p: R472.2 ; also on sheet 33
FPGA_VID_ALERTN: U34.N4(IO_2_N4/PLL_L_CLKOUTP/DIFFIO_RX_L59P) ; also on sheet 77
FX2_PD0: U38.16(NC1) ; also on sheet 49
FX2_PD1: U38.3(NC2) ; also on sheet 49
FX2_PD2: U38.9(NC3) ; also on sheet 49
FX2_PD3: U38.12(NC4) ; also on sheet 49
G2_EN: R6231.2 R6232.2 R6233.2 R6234.2 R6235.2 R6236.2 R6237.2 U34.F10(IO_7_F10/DIFFIO_RX_T28P)
G3_EN: R6238.2 R6239.2 R6240.2 R6249.2 R6253.1 R6254.1 U34.B13(IO_7_B13/DIFFIO_RX_T30P)
G4_EN: R6241.2 R6242.2 R6243.2 R6244.2 R6245.2 R6246.2 R6247.2 R6248.2 U34.B8(IO_8_B8/DEV_OE/DIFFIO_RX_T44P)
I2C2_SCL: EU1.12(SCL) EU2.12(SCL) U43.6(SCL) ; also on sheet 27 32 46 48 50
I2C2_SDA: EU1.11(SDA) EU2.11(SDA) U43.5(SDA) ; also on sheet 27 32 46 48 50
IO_1p8V_EN: R6242.1 ; also on sheet 67
IO_3p3V: C561.1 C567.1 R462.2 R463.2 R464.2 U42.19(VCC) U43.8(VCC) ; also on sheet 25 26 27 30 31 32 43 44 46 47 48 73
IO_3p3V_EN: R6243.1 ; also on sheet 73
JTAGEN: R6189.1 R6190.2 U34.G6(IO_1B_G6/JTAGEN)
M10_1V2_CLK: R441.2 U40.3(IO_VL2) ; also on sheet 12
M10_1V2_DATA0: R439.2 U40.4(IO_VL3) ; also on sheet 12
M10_1V2_DATA1: R438.2 U40.5(IO_VL4) ; also on sheet 12
M10_1V2_DATA2: R437.2 U40.6(IO_VL5) ; also on sheet 12
M10_1V2_DATA3: R436.2 U40.7(IO_VL6) ; also on sheet 12
M10_1V2_GPIO0: U40.8(IO_VL7) ; also on sheet 12
M10_1V2_GPIO1: U40.9(IO_VL8) ; also on sheet 12
M10_1V2_SSN: R442.2 U40.1(IO_VL1) ; also on sheet 12
M10_1V2_VCCDPLL: C541.1 C542.1 C543.1 C544.1 C545.1 L13.2 U34.D4(VCCD_PLL3_) U34.D13(VCCD_PLL2_) U34.M5(VCCD_PLL1_) U34.N13(VCCD_PLL4_)
M10_CONF_DONE: R423.1 U34.E7(IO_8_E7/CONF_DONE/DIFFIO_RX_T50N) ; also on sheet 48
M10_CRC_ERROR: U34.C5(IO_8_C5/CRC_ERROR/DIFFIO_RX_T48N) ; also on sheet 77
M10_GPIO0: U40.13(IO_VCC7) ; also on sheet 48
M10_GPIO1: U40.12(IO_VCC8) ; also on sheet 48
M10_VCCINT: C546.1 L14.2 U34.F6(VCCINT_)
MAX10_VCCA_2.5V: C523.1 C524.1 C525.1 C526.1 C527.1 L11.2 U34.D5(VCCA3_) U34.E12(VCCA2_) U34.L5(VCCA1_) U34.M12(VCCA4_)
MAX10_VCCA_ADC_2.5V: C528.1 L12.2 U34.E5(VCCA_ADC_)
NIOS_UART_RX: J14.2 R6211.2 U34.F12(IO_7_F12/DIFFIO_RX_T17N)
NIOS_UART_TX: J14.1 R6210.2 U34.A14(IO_7)
PCIE_EP_12V: C588.1 D13.1(C) R487.1 R503.2 TP960.1 TP961.1 U49.1(S1) U49.2(S2) U49.3(S3) U51.2(IN) ; also on sheet 30
PCIE_EP_JTAG_TCK: R451.1 U41.1(IN_1A) ; also on sheet 30
PCIE_EP_JTAG_TDI: R445.2 U41.3(IN_2A) ; also on sheet 30
PCIE_EP_JTAG_TDO: R443.1 ; also on sheet 30
PCIE_EP_JTAG_TMS: R435.2 U39.1(IN_1A) ; also on sheet 30
POWER_ON: R482.2 R495.2 R504.2 SW6.5 ; also on sheet 50
STRAP_1_PCLASS1: R2206.2 R2734.2 ; also on sheet 50
STRAP_3_CVL_PRSNT0_n: R2735.1 U34.L6(IO_2_L6/DIFFIO_RX_L41P) ; also on sheet 50
TEMP1_THERMn: EU1.9(~{THERM}) R453.1 ; also on sheet 48
TEMP2_THERMn: EU2.9(~{THERM}) R465.1 ; also on sheet 48
USB_DISABLEn: R6183.2 R6184.2 ; also on sheet 50
USB_MAX_JTAGSEL: U34.F11(IO_7_F11/DIFFIO_RX_T17P) U38.15(IN) ; also on sheet 50
USB_MAX_TCK: U34.H3(IO_1B_H3/TCK/DIFFIO_RX_L17P) U38.2(COM1)
USB_MAX_TDI: U34.G1(IO_1B_G1/TDI/DIFFIO_RX_L18N) U38.7(COM3)
USB_MAX_TDO: U34.H1(IO_1B_H1/TDO/DIFFIO_RX_L18P) U38.10(COM4)
USB_MAX_TMS: U34.H2(IO_1B_H2/TMS/DIFFIO_RX_L17N) U38.5(COM2)
VTT_DDR4_CH1_EN: R6246.1 ; also on sheet 72
VTT_DDR4_CH2_EN: R6247.1 ; also on sheet 72
VTT_DDR4_CH3_EN: R6248.1 ; also on sheet 72
N31415897: Q13.4(G) R483.1
N31415950: C581.1 R483.2 U48.1(GATE)
N31416024: Q14.3(DRAIN) R485.2 U48.5(~{SHDN})
N31416063: C582.2 R490.1 U48.6(VSS)
N31416065: C587.1 R487.2 R488.1 R489.2
N31416086: Q14.1(GATE) R489.1
N32052935: C563.1 EU1.2(DXP1) R454.1
N32053041: C563.2 EU1.3(DXN1) R455.1
N32230321: R480.1 U45.4(G) U47.5(GATE)
N32230341: R479.2 R484.2 U47.3(UV)
N32230392: R484.1 R486.1 U47.2(OV)
N32230759: U44.4(G) U46.3(GATE)
N32232827: U49.4(G) U51.3(GATE)
N32233406: R493.1 U50.4(G) U52.5(GATE)
N32233436: R492.2 R496.2 U52.3(UV)
N32233467: R491.2 R495.1 U52.8(~{SHDN})
N32233496: R496.1 R497.1 U52.2(OV)
N32233958: R501.1 SW6.4
N32406903: R503.1 SW6.6
N32408103: R478.2 R482.1 U47.8(~{SHDN})
N32408438: R500.2 R502.2 U53.3(INA+)
N32408441: R502.1 R505.1 U53.4(INB-)
N37925832: C579.2 R480.2
N37926031: C589.2 R493.2
N40362320: R440.2 U39.6(OUT_1Y)
N40362341: R443.2 U39.4(OUT_2Y)
N40362434: R446.2 U41.6(OUT_1Y)
N40362458: R447.2 U41.4(OUT_2Y)
N40489939: R444.2 U40.10(EN)
N40492779: R457.2 U42.10(EN)
N40559506: R462.1 R467.2 U43.3(E2)
N40559508: R463.1 R468.2 U43.2(E1)
N40559510: R464.1 R469.2 U43.1(E0)
N40559585: R466.1 U43.7(WC_N)
N41105372: C564.1 EU1.4(DXP2) R456.1
N41105376: C564.2 EU1.5(DXN2) R458.1
N41105458: C566.1 EU1.6(DXP3) R459.1
N41105462: C566.2 EU1.7(DXN3) R461.1
N41106635: EU1.10(ADD) R460.1
N41107356: C568.2 EU2.3(DXN1) R471.1
N41107358: C568.1 EU2.2(DXP1) R470.1
N41107415: C569.2 EU2.5(DXN2) R473.1
N41107417: C569.1 EU2.4(DXP2) R472.1
N41107474: C571.2 EU2.7(DXN3) R475.1
N41107476: C571.1 EU2.6(DXP3) R474.1
N41107506: EU2.10(ADD) R476.1
N45214136: R982.2 U42.14(IO_VCC6)
N46993584: J10.8 R2734.1
N46996106: J10.2 R6183.1
N46996953: J10.7 R2735.2
N49300504: R6186.1 U34.E8(INPUT_ONLY_8_E8/NCONFIG)
N49304849: R6187.2 R6188.1 U34.F8(IO_8_F8/CONFIG_SEL)
N49328720: R6185.1 U34.F7(IO_8_F7/NSTATUS/DIFFIO_RX_T50P)
N52524319: J10.1 R2736.1

Not connected (* = marked no-connect by the designer): J10 6*; SW6 1* 2* 3*; U34 A13(IO_7_A13/DIFFIO_RX_T30N)*; U42 8(IO_VL7)* 13(IO_VCC7)*; U46 5(NC)*; U48 3(NC1)* 7(NC2)*; U51 5(NC)*

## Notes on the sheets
sheet 51
- MAX 10 PWR Manager 1
- 3.3V
- 3.3V
- 3.3V
- 3.3V
- (TCK)
- (TMS)
- (TDI)
- (TDO)
- IN = "0"   NC <--> COM
  IN = "1"   NO <--> COM
- USB_MAX_JTAG = "1", Debug mode.
  EXT UBII is disabled on SYS MAX10.
- External JTAG  Header
- P1V2
sheet 52
- Level Shifter
- From PCIe
- To MAX10
- To PCIE
- From MAX10
- Schmitt Buffer
- From PCIe
- To MAX10
- From PCIe
- To MAX10
- Schmitt Buffer
- Core A
- Core C
- F TILE
- I2C ADDR = 38
- EEPROM
- R TILE
   14C
- R TILE
   15C
- Vih = 0.7VCC = 2.31V
  Vil = 0.3VCC = 0.99V
- I2C 7-bit Addr = 0x57/0x5F
  I2C 8-bit Addr = 0xAE/0xBE
- R TILE
   15A
- I2C ADDR = 3A
- Board Temp Sensor
sheet 53
- Power - Select Power Input
- H = 1.1mm
  Place on bottom side
- H = 1.0mm
  Place on bottom side
- PCIe Specs: 12.5A +5%/-8%
- Vgs(th) = 2.5V/3.7V/4.5V
- 12V Holding Caps
- Chold = 1160uF for 12_G1
- When 16V,   EN = 1.96V
  When 15V,   EN = 1.84V
  When 14V,   EN = 1.72V
  When 13V,   EN = 1.59V
  When 12V,   EN = 1.47V
  When 11V,   EN = 1.35V
  When 10V,   EN = 1.23V
- When 12V_PCIE = 12V
  EN_12V_G1G2_L = 1.47V
- Vshdn_absmax = 100V
- VGS(th) max = 0.85V
- 12V from PCIe Slot
- H = 1.1mm
  Place on bottom side
- H = 1.0mm
  Place on bottom side
- Vshdn_th = 0.6V/1.2V/2V
- Power On Switch
- Condition   Aux    PCIe    PWR_SW   Start_SEQ
- Bench     Y       N       ON      12V_G1_UV/OV_PG=Y
- Bench     Y       N       OFF      N
- SLOT      Y       Y       X       12V_G1_UV/OV_PG=Y
- SLOT      N       Y       ON       N
- SLOT      N       Y       OFF     12V_G1_UV/OV_PG=N
- Chold = 900uF for 12_G2
- ON
- OFF
- 12V_G1 > 10.46V : OUTA = "1";
  12V_G1 < 13.77V:  OUTB = "1";
  PWR MAX10 get both "1" to start the power seq
